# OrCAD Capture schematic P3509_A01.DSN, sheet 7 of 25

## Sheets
7 0018_CAMERA: size Custom
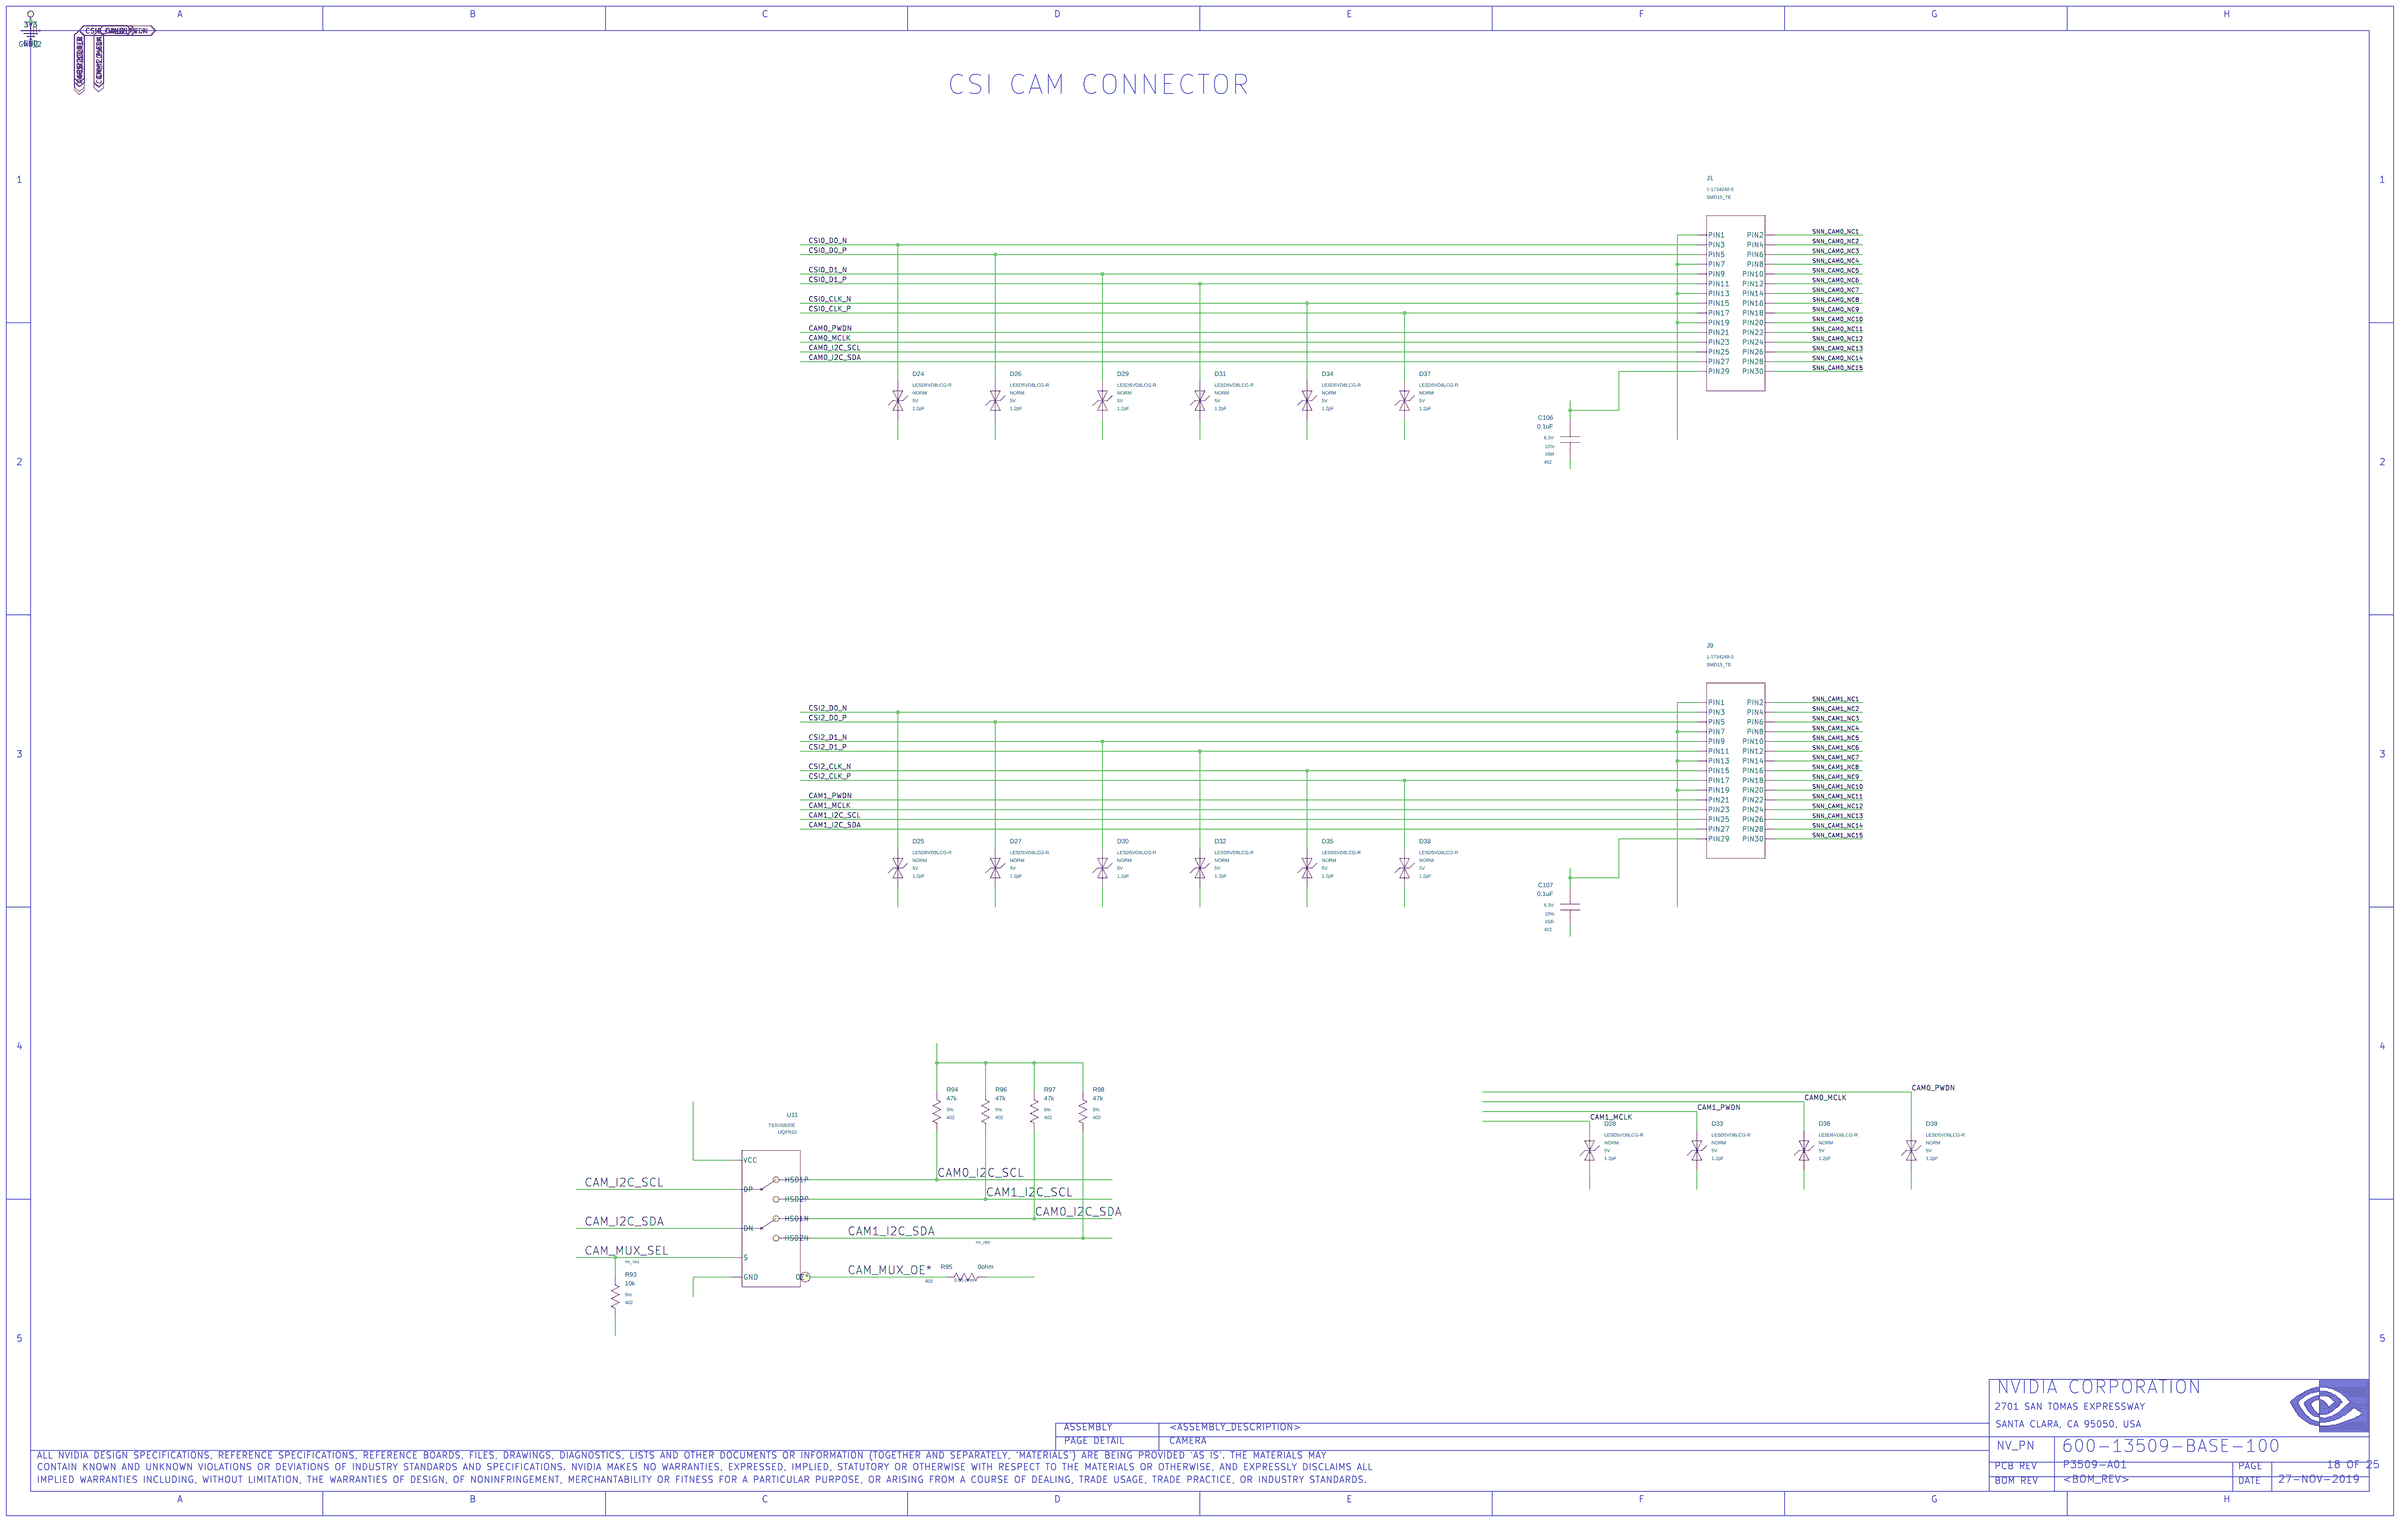
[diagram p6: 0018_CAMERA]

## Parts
C106  0.1uF  [402]
C107  0.1uF  [402]
D24  D_ESD  [DIODE_SMD_010X060]
D25  D_ESD  [DIODE_SMD_010X060]
D26  D_ESD  [DIODE_SMD_010X060]
D27  D_ESD  [DIODE_SMD_010X060]
D28  D_ESD  [DIODE_SMD_010X060]
D29  D_ESD  [DIODE_SMD_010X060]
D30  D_ESD  [DIODE_SMD_010X060]
D31  D_ESD  [DIODE_SMD_010X060]
D32  D_ESD  [DIODE_SMD_010X060]
D33  D_ESD  [DIODE_SMD_010X060]
D34  D_ESD  [DIODE_SMD_010X060]
D35  D_ESD  [DIODE_SMD_010X060]
D36  D_ESD  [DIODE_SMD_010X060]
D37  D_ESD  [DIODE_SMD_010X060]
D38  D_ESD  [DIODE_SMD_010X060]
D39  D_ESD  [DIODE_SMD_010X060]
J1  CON_FPC_15  [CON_FFC_030_SMD_ST_F_P010_ZIF]
J9  CON_FPC_15  [CON_FFC_030_SMD_ST_F_P010_ZIF]
R93  10k  [402]
R94  47k  [402]
R95  0ohm  [402]
R96  47k  [402]
R97  47k  [402]
R98  47k  [402]
U11  U_SW_ANA_USB  [QFN010R_P040_0018X0014]

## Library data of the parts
C106 = C#1_v2: ASSEMBLY: CAM; CDS_LIB: discrete; CDS_PART_NAME: C_0402-0.1UF,X5R,10%,6.3V,039-0007-000; CDS_PHYS_PART_NAME: C_0402-0.1UF,X5R,10%,6.3V,039-0007-000-0.1UF,039-0007-000; CDS_SEC: 1; CHIPS_PART_NAME: C; DEVICE_TYPENAME: C_0402-01UFX5R1063V039-0007-000-01UF039-0007-000; DRAWING: #NAME?; ESL: N/A; ESR: N/A; MAT: X5R; MAX_VOLTAGE: 6.3V; NV_PN: 039-0007-000; PATH: I89; PHYS_PAGE: 18; ROT: 2; SEC: 1; SIGNAL_MODEL: nv_cap; TOL: 10%; VER: 1; XY: (-4100,5400)
C107 = C#1_v2: ASSEMBLY: CAM; CDS_LIB: discrete; CDS_PART_NAME: C_0402-0.1UF,X5R,10%,6.3V,039-0007-000; CDS_PHYS_PART_NAME: C_0402-0.1UF,X5R,10%,6.3V,039-0007-000-0.1UF,039-0007-000; CDS_SEC: 1; CHIPS_PART_NAME: C; DEVICE_TYPENAME: C_0402-01UFX5R1063V039-0007-000-01UF039-0007-000; DRAWING: #NAME?; ESL: N/A; ESR: N/A; MAT: X5R; MAX_VOLTAGE: 6.3V; NV_PN: 039-0007-000; PATH: I94; PHYS_PAGE: 18; ROT: 2; SEC: 1; SIGNAL_MODEL: nv_cap; TOL: 10%; VER: 1; XY: (-4100,3000)
D24 = D_ESD: ASSEMBLY: CAM; BREAKDOWN_VOLTAGE_MIN_TYP: 5.5V; CAPACITANCE_MAX_TYP: 1.2pF; CDS_LIB: discrete; CDS_PART_NAME: D_ESD_NORM-LESD5VD8LCG-R,1 LINE,BI-DIRECTIONAL,5V,0.05UA,5.5V,10V@2A,1.2PF,090-0172-000; CDS_PHYS_PART_NAME: D_ESD_NORM-LESD5VD8LCG-R,1 LINE,BI-DIRECTIONAL,5V,0.05UA,5.5V,10V@2A,1.2PF,090-0172-000-090-0172-000; CDS_SEC: 1; CLAMPING_VOLTAGE: 10V@2A; CONFIGURATION: 1 Line; DEVICE_TYPENAME: D_ESD_NORM-LESD5VD8LCG-R1LINEBI-DIRECTIONAL5V005UA55V10V2A12PF090-0172-000-090-0172-000; DRAWING: #NAME?; MAX_REVERSE_LEAKAGE_CURRENT: 0.05uA; MAX_REVERSE_VOLTAGE: 5V; NV_NAME: LESD5VD8LCG-R; NV_PN: 090-0172-000; PACK_TYPE: NORM; PATH: I112; PHYS_PAGE: 18; POLARITY: Bi-Directional; ROT: 0; SEC: 1; VER: 2; XY: (-7550,5600)
D25 = D_ESD: ASSEMBLY: CAM; BREAKDOWN_VOLTAGE_MIN_TYP: 5.5V; CAPACITANCE_MAX_TYP: 1.2pF; CDS_LIB: discrete; CDS_PART_NAME: D_ESD_NORM-LESD5VD8LCG-R,1 LINE,BI-DIRECTIONAL,5V,0.05UA,5.5V,10V@2A,1.2PF,090-0172-000; CDS_PHYS_PART_NAME: D_ESD_NORM-LESD5VD8LCG-R,1 LINE,BI-DIRECTIONAL,5V,0.05UA,5.5V,10V@2A,1.2PF,090-0172-000-090-0172-000; CDS_SEC: 1; CLAMPING_VOLTAGE: 10V@2A; CONFIGURATION: 1 Line; DEVICE_TYPENAME: D_ESD_NORM-LESD5VD8LCG-R1LINEBI-DIRECTIONAL5V005UA55V10V2A12PF090-0172-000-090-0172-000; DRAWING: #NAME?; MAX_REVERSE_LEAKAGE_CURRENT: 0.05uA; MAX_REVERSE_VOLTAGE: 5V; NV_NAME: LESD5VD8LCG-R; NV_PN: 090-0172-000; PACK_TYPE: NORM; PATH: I146; PHYS_PAGE: 18; POLARITY: Bi-Directional; ROT: 0; SEC: 1; VER: 2; XY: (-7550,3200)
D26 = D_ESD: ASSEMBLY: CAM; BREAKDOWN_VOLTAGE_MIN_TYP: 5.5V; CAPACITANCE_MAX_TYP: 1.2pF; CDS_LIB: discrete; CDS_PART_NAME: D_ESD_NORM-LESD5VD8LCG-R,1 LINE,BI-DIRECTIONAL,5V,0.05UA,5.5V,10V@2A,1.2PF,090-0172-000; CDS_PHYS_PART_NAME: D_ESD_NORM-LESD5VD8LCG-R,1 LINE,BI-DIRECTIONAL,5V,0.05UA,5.5V,10V@2A,1.2PF,090-0172-000-090-0172-000; CDS_SEC: 1; CLAMPING_VOLTAGE: 10V@2A; CONFIGURATION: 1 Line; DEVICE_TYPENAME: D_ESD_NORM-LESD5VD8LCG-R1LINEBI-DIRECTIONAL5V005UA55V10V2A12PF090-0172-000-090-0172-000; DRAWING: #NAME?; MAX_REVERSE_LEAKAGE_CURRENT: 0.05uA; MAX_REVERSE_VOLTAGE: 5V; NV_NAME: LESD5VD8LCG-R; NV_PN: 090-0172-000; PACK_TYPE: NORM; PATH: I111; PHYS_PAGE: 18; POLARITY: Bi-Directional; ROT: 0; SEC: 1; VER: 2; XY: (-7050,5600)
D27 = D_ESD: ASSEMBLY: CAM; BREAKDOWN_VOLTAGE_MIN_TYP: 5.5V; CAPACITANCE_MAX_TYP: 1.2pF; CDS_LIB: discrete; CDS_PART_NAME: D_ESD_NORM-LESD5VD8LCG-R,1 LINE,BI-DIRECTIONAL,5V,0.05UA,5.5V,10V@2A,1.2PF,090-0172-000; CDS_PHYS_PART_NAME: D_ESD_NORM-LESD5VD8LCG-R,1 LINE,BI-DIRECTIONAL,5V,0.05UA,5.5V,10V@2A,1.2PF,090-0172-000-090-0172-000; CDS_SEC: 1; CLAMPING_VOLTAGE: 10V@2A; CONFIGURATION: 1 Line; DEVICE_TYPENAME: D_ESD_NORM-LESD5VD8LCG-R1LINEBI-DIRECTIONAL5V005UA55V10V2A12PF090-0172-000-090-0172-000; DRAWING: #NAME?; MAX_REVERSE_LEAKAGE_CURRENT: 0.05uA; MAX_REVERSE_VOLTAGE: 5V; NV_NAME: LESD5VD8LCG-R; NV_PN: 090-0172-000; PACK_TYPE: NORM; PATH: I144; PHYS_PAGE: 18; POLARITY: Bi-Directional; ROT: 0; SEC: 1; VER: 2; XY: (-7050,3200)
D28 = D_ESD: ASSEMBLY: CAM; BREAKDOWN_VOLTAGE_MIN_TYP: 5.5V; CAPACITANCE_MAX_TYP: 1.2pF; CDS_LIB: discrete; CDS_PART_NAME: D_ESD_NORM-LESD5VD8LCG-R,1 LINE,BI-DIRECTIONAL,5V,0.05UA,5.5V,10V@2A,1.2PF,090-0172-000; CDS_PHYS_PART_NAME: D_ESD_NORM-LESD5VD8LCG-R,1 LINE,BI-DIRECTIONAL,5V,0.05UA,5.5V,10V@2A,1.2PF,090-0172-000-090-0172-000; CDS_SEC: 1; CLAMPING_VOLTAGE: 10V@2A; CONFIGURATION: 1 Line; DEVICE_TYPENAME: D_ESD_NORM-LESD5VD8LCG-R1LINEBI-DIRECTIONAL5V005UA55V10V2A12PF090-0172-000-090-0172-000; DRAWING: #NAME?; MAX_REVERSE_LEAKAGE_CURRENT: 0.05uA; MAX_REVERSE_VOLTAGE: 5V; NV_NAME: LESD5VD8LCG-R; NV_PN: 090-0172-000; PACK_TYPE: NORM; PATH: I142; PHYS_PAGE: 18; POLARITY: Bi-Directional; ROT: 0; SEC: 1; VER: 2; XY: (-4000,1750)
D29 = D_ESD: ASSEMBLY: CAM; BREAKDOWN_VOLTAGE_MIN_TYP: 5.5V; CAPACITANCE_MAX_TYP: 1.2pF; CDS_LIB: discrete; CDS_PART_NAME: D_ESD_NORM-LESD5VD8LCG-R,1 LINE,BI-DIRECTIONAL,5V,0.05UA,5.5V,10V@2A,1.2PF,090-0172-000; CDS_PHYS_PART_NAME: D_ESD_NORM-LESD5VD8LCG-R,1 LINE,BI-DIRECTIONAL,5V,0.05UA,5.5V,10V@2A,1.2PF,090-0172-000-090-0172-000; CDS_SEC: 1; CLAMPING_VOLTAGE: 10V@2A; CONFIGURATION: 1 Line; DEVICE_TYPENAME: D_ESD_NORM-LESD5VD8LCG-R1LINEBI-DIRECTIONAL5V005UA55V10V2A12PF090-0172-000-090-0172-000; DRAWING: #NAME?; MAX_REVERSE_LEAKAGE_CURRENT: 0.05uA; MAX_REVERSE_VOLTAGE: 5V; NV_NAME: LESD5VD8LCG-R; NV_PN: 090-0172-000; PACK_TYPE: NORM; PATH: I108; PHYS_PAGE: 18; POLARITY: Bi-Directional; ROT: 0; SEC: 1; VER: 2; XY: (-6500,5600)
D30 = D_ESD: ASSEMBLY: CAM; BREAKDOWN_VOLTAGE_MIN_TYP: 5.5V; CAPACITANCE_MAX_TYP: 1.2pF; CDS_LIB: discrete; CDS_PART_NAME: D_ESD_NORM-LESD5VD8LCG-R,1 LINE,BI-DIRECTIONAL,5V,0.05UA,5.5V,10V@2A,1.2PF,090-0172-000; CDS_PHYS_PART_NAME: D_ESD_NORM-LESD5VD8LCG-R,1 LINE,BI-DIRECTIONAL,5V,0.05UA,5.5V,10V@2A,1.2PF,090-0172-000-090-0172-000; CDS_SEC: 1; CLAMPING_VOLTAGE: 10V@2A; CONFIGURATION: 1 Line; DEVICE_TYPENAME: D_ESD_NORM-LESD5VD8LCG-R1LINEBI-DIRECTIONAL5V005UA55V10V2A12PF090-0172-000-090-0172-000; DRAWING: #NAME?; MAX_REVERSE_LEAKAGE_CURRENT: 0.05uA; MAX_REVERSE_VOLTAGE: 5V; NV_NAME: LESD5VD8LCG-R; NV_PN: 090-0172-000; PACK_TYPE: NORM; PATH: I134; PHYS_PAGE: 18; POLARITY: Bi-Directional; ROT: 0; SEC: 1; VER: 2; XY: (-6500,3200)
D31 = D_ESD: ASSEMBLY: CAM; BREAKDOWN_VOLTAGE_MIN_TYP: 5.5V; CAPACITANCE_MAX_TYP: 1.2pF; CDS_LIB: discrete; CDS_PART_NAME: D_ESD_NORM-LESD5VD8LCG-R,1 LINE,BI-DIRECTIONAL,5V,0.05UA,5.5V,10V@2A,1.2PF,090-0172-000; CDS_PHYS_PART_NAME: D_ESD_NORM-LESD5VD8LCG-R,1 LINE,BI-DIRECTIONAL,5V,0.05UA,5.5V,10V@2A,1.2PF,090-0172-000-090-0172-000; CDS_SEC: 1; CLAMPING_VOLTAGE: 10V@2A; CONFIGURATION: 1 Line; DEVICE_TYPENAME: D_ESD_NORM-LESD5VD8LCG-R1LINEBI-DIRECTIONAL5V005UA55V10V2A12PF090-0172-000-090-0172-000; DRAWING: #NAME?; MAX_REVERSE_LEAKAGE_CURRENT: 0.05uA; MAX_REVERSE_VOLTAGE: 5V; NV_NAME: LESD5VD8LCG-R; NV_PN: 090-0172-000; PACK_TYPE: NORM; PATH: I107; PHYS_PAGE: 18; POLARITY: Bi-Directional; ROT: 0; SEC: 1; VER: 2; XY: (-6000,5600)
D32 = D_ESD: ASSEMBLY: CAM; BREAKDOWN_VOLTAGE_MIN_TYP: 5.5V; CAPACITANCE_MAX_TYP: 1.2pF; CDS_LIB: discrete; CDS_PART_NAME: D_ESD_NORM-LESD5VD8LCG-R,1 LINE,BI-DIRECTIONAL,5V,0.05UA,5.5V,10V@2A,1.2PF,090-0172-000; CDS_PHYS_PART_NAME: D_ESD_NORM-LESD5VD8LCG-R,1 LINE,BI-DIRECTIONAL,5V,0.05UA,5.5V,10V@2A,1.2PF,090-0172-000-090-0172-000; CDS_SEC: 1; CLAMPING_VOLTAGE: 10V@2A; CONFIGURATION: 1 Line; DEVICE_TYPENAME: D_ESD_NORM-LESD5VD8LCG-R1LINEBI-DIRECTIONAL5V005UA55V10V2A12PF090-0172-000-090-0172-000; DRAWING: #NAME?; MAX_REVERSE_LEAKAGE_CURRENT: 0.05uA; MAX_REVERSE_VOLTAGE: 5V; NV_NAME: LESD5VD8LCG-R; NV_PN: 090-0172-000; PACK_TYPE: NORM; PATH: I132; PHYS_PAGE: 18; POLARITY: Bi-Directional; ROT: 0; SEC: 1; VER: 2; XY: (-6000,3200)
D33 = D_ESD: ASSEMBLY: CAM; BREAKDOWN_VOLTAGE_MIN_TYP: 5.5V; CAPACITANCE_MAX_TYP: 1.2pF; CDS_LIB: discrete; CDS_PART_NAME: D_ESD_NORM-LESD5VD8LCG-R,1 LINE,BI-DIRECTIONAL,5V,0.05UA,5.5V,10V@2A,1.2PF,090-0172-000; CDS_PHYS_PART_NAME: D_ESD_NORM-LESD5VD8LCG-R,1 LINE,BI-DIRECTIONAL,5V,0.05UA,5.5V,10V@2A,1.2PF,090-0172-000-090-0172-000; CDS_SEC: 1; CLAMPING_VOLTAGE: 10V@2A; CONFIGURATION: 1 Line; DEVICE_TYPENAME: D_ESD_NORM-LESD5VD8LCG-R1LINEBI-DIRECTIONAL5V005UA55V10V2A12PF090-0172-000-090-0172-000; DRAWING: #NAME?; MAX_REVERSE_LEAKAGE_CURRENT: 0.05uA; MAX_REVERSE_VOLTAGE: 5V; NV_NAME: LESD5VD8LCG-R; NV_PN: 090-0172-000; PACK_TYPE: NORM; PATH: I140; PHYS_PAGE: 18; POLARITY: Bi-Directional; ROT: 0; SEC: 1; VER: 2; XY: (-3450,1750)
D34 = D_ESD: ASSEMBLY: CAM; BREAKDOWN_VOLTAGE_MIN_TYP: 5.5V; CAPACITANCE_MAX_TYP: 1.2pF; CDS_LIB: discrete; CDS_PART_NAME: D_ESD_NORM-LESD5VD8LCG-R,1 LINE,BI-DIRECTIONAL,5V,0.05UA,5.5V,10V@2A,1.2PF,090-0172-000; CDS_PHYS_PART_NAME: D_ESD_NORM-LESD5VD8LCG-R,1 LINE,BI-DIRECTIONAL,5V,0.05UA,5.5V,10V@2A,1.2PF,090-0172-000-090-0172-000; CDS_SEC: 1; CLAMPING_VOLTAGE: 10V@2A; CONFIGURATION: 1 Line; DEVICE_TYPENAME: D_ESD_NORM-LESD5VD8LCG-R1LINEBI-DIRECTIONAL5V005UA55V10V2A12PF090-0172-000-090-0172-000; DRAWING: #NAME?; MAX_REVERSE_LEAKAGE_CURRENT: 0.05uA; MAX_REVERSE_VOLTAGE: 5V; NV_NAME: LESD5VD8LCG-R; NV_PN: 090-0172-000; PACK_TYPE: NORM; PATH: I103; PHYS_PAGE: 18; POLARITY: Bi-Directional; ROT: 0; SEC: 1; VER: 2; XY: (-5450,5600)
D35 = D_ESD: ASSEMBLY: CAM; BREAKDOWN_VOLTAGE_MIN_TYP: 5.5V; CAPACITANCE_MAX_TYP: 1.2pF; CDS_LIB: discrete; CDS_PART_NAME: D_ESD_NORM-LESD5VD8LCG-R,1 LINE,BI-DIRECTIONAL,5V,0.05UA,5.5V,10V@2A,1.2PF,090-0172-000; CDS_PHYS_PART_NAME: D_ESD_NORM-LESD5VD8LCG-R,1 LINE,BI-DIRECTIONAL,5V,0.05UA,5.5V,10V@2A,1.2PF,090-0172-000-090-0172-000; CDS_SEC: 1; CLAMPING_VOLTAGE: 10V@2A; CONFIGURATION: 1 Line; DEVICE_TYPENAME: D_ESD_NORM-LESD5VD8LCG-R1LINEBI-DIRECTIONAL5V005UA55V10V2A12PF090-0172-000-090-0172-000; DRAWING: #NAME?; MAX_REVERSE_LEAKAGE_CURRENT: 0.05uA; MAX_REVERSE_VOLTAGE: 5V; NV_NAME: LESD5VD8LCG-R; NV_PN: 090-0172-000; PACK_TYPE: NORM; PATH: I131; PHYS_PAGE: 18; POLARITY: Bi-Directional; ROT: 0; SEC: 1; VER: 2; XY: (-5450,3200)
D36 = D_ESD: ASSEMBLY: CAM; BREAKDOWN_VOLTAGE_MIN_TYP: 5.5V; CAPACITANCE_MAX_TYP: 1.2pF; CDS_LIB: discrete; CDS_PART_NAME: D_ESD_NORM-LESD5VD8LCG-R,1 LINE,BI-DIRECTIONAL,5V,0.05UA,5.5V,10V@2A,1.2PF,090-0172-000; CDS_PHYS_PART_NAME: D_ESD_NORM-LESD5VD8LCG-R,1 LINE,BI-DIRECTIONAL,5V,0.05UA,5.5V,10V@2A,1.2PF,090-0172-000-090-0172-000; CDS_SEC: 1; CLAMPING_VOLTAGE: 10V@2A; CONFIGURATION: 1 Line; DEVICE_TYPENAME: D_ESD_NORM-LESD5VD8LCG-R1LINEBI-DIRECTIONAL5V005UA55V10V2A12PF090-0172-000-090-0172-000; DRAWING: #NAME?; MAX_REVERSE_LEAKAGE_CURRENT: 0.05uA; MAX_REVERSE_VOLTAGE: 5V; NV_NAME: LESD5VD8LCG-R; NV_PN: 090-0172-000; PACK_TYPE: NORM; PATH: I138; PHYS_PAGE: 18; POLARITY: Bi-Directional; ROT: 0; SEC: 1; VER: 2; XY: (-2900,1750)
D37 = D_ESD: ASSEMBLY: CAM; BREAKDOWN_VOLTAGE_MIN_TYP: 5.5V; CAPACITANCE_MAX_TYP: 1.2pF; CDS_LIB: discrete; CDS_PART_NAME: D_ESD_NORM-LESD5VD8LCG-R,1 LINE,BI-DIRECTIONAL,5V,0.05UA,5.5V,10V@2A,1.2PF,090-0172-000; CDS_PHYS_PART_NAME: D_ESD_NORM-LESD5VD8LCG-R,1 LINE,BI-DIRECTIONAL,5V,0.05UA,5.5V,10V@2A,1.2PF,090-0172-000-090-0172-000; CDS_SEC: 1; CLAMPING_VOLTAGE: 10V@2A; CONFIGURATION: 1 Line; DEVICE_TYPENAME: D_ESD_NORM-LESD5VD8LCG-R1LINEBI-DIRECTIONAL5V005UA55V10V2A12PF090-0172-000-090-0172-000; DRAWING: #NAME?; MAX_REVERSE_LEAKAGE_CURRENT: 0.05uA; MAX_REVERSE_VOLTAGE: 5V; NV_NAME: LESD5VD8LCG-R; NV_PN: 090-0172-000; PACK_TYPE: NORM; PATH: I102; PHYS_PAGE: 18; POLARITY: Bi-Directional; ROT: 0; SEC: 1; VER: 2; XY: (-4950,5600)
D38 = D_ESD: ASSEMBLY: CAM; BREAKDOWN_VOLTAGE_MIN_TYP: 5.5V; CAPACITANCE_MAX_TYP: 1.2pF; CDS_LIB: discrete; CDS_PART_NAME: D_ESD_NORM-LESD5VD8LCG-R,1 LINE,BI-DIRECTIONAL,5V,0.05UA,5.5V,10V@2A,1.2PF,090-0172-000; CDS_PHYS_PART_NAME: D_ESD_NORM-LESD5VD8LCG-R,1 LINE,BI-DIRECTIONAL,5V,0.05UA,5.5V,10V@2A,1.2PF,090-0172-000-090-0172-000; CDS_SEC: 1; CLAMPING_VOLTAGE: 10V@2A; CONFIGURATION: 1 Line; DEVICE_TYPENAME: D_ESD_NORM-LESD5VD8LCG-R1LINEBI-DIRECTIONAL5V005UA55V10V2A12PF090-0172-000-090-0172-000; DRAWING: #NAME?; MAX_REVERSE_LEAKAGE_CURRENT: 0.05uA; MAX_REVERSE_VOLTAGE: 5V; NV_NAME: LESD5VD8LCG-R; NV_PN: 090-0172-000; PACK_TYPE: NORM; PATH: I129; PHYS_PAGE: 18; POLARITY: Bi-Directional; ROT: 0; SEC: 1; VER: 2; XY: (-4950,3200)
D39 = D_ESD: ASSEMBLY: CAM; BREAKDOWN_VOLTAGE_MIN_TYP: 5.5V; CAPACITANCE_MAX_TYP: 1.2pF; CDS_LIB: discrete; CDS_PART_NAME: D_ESD_NORM-LESD5VD8LCG-R,1 LINE,BI-DIRECTIONAL,5V,0.05UA,5.5V,10V@2A,1.2PF,090-0172-000; CDS_PHYS_PART_NAME: D_ESD_NORM-LESD5VD8LCG-R,1 LINE,BI-DIRECTIONAL,5V,0.05UA,5.5V,10V@2A,1.2PF,090-0172-000-090-0172-000; CDS_SEC: 1; CLAMPING_VOLTAGE: 10V@2A; CONFIGURATION: 1 Line; DEVICE_TYPENAME: D_ESD_NORM-LESD5VD8LCG-R1LINEBI-DIRECTIONAL5V005UA55V10V2A12PF090-0172-000-090-0172-000; DRAWING: #NAME?; MAX_REVERSE_LEAKAGE_CURRENT: 0.05uA; MAX_REVERSE_VOLTAGE: 5V; NV_NAME: LESD5VD8LCG-R; NV_PN: 090-0172-000; PACK_TYPE: NORM; PATH: I136; PHYS_PAGE: 18; POLARITY: Bi-Directional; ROT: 0; SEC: 1; VER: 2; XY: (-2350,1750)
J1 = CON_FPC_15: ANGLE: 0; ASSEMBLY: CAM; CDS_LIB: electro_mechanic; CDS_PART_NAME: CON_FPC_15_SMD15_TE-1-1734248-5,FEMALE,1MM,0,YES,YES,[ ],NO,NO,N/A,N/A,080-1669-000; CDS_PHYS_PART_NAME: CON_FPC_15_SMD15_TE-1-1734248-5,FEMALE,1MM,0,YES,YES,[ ],NO,NO,N/A,N/A,080-1669-000-080-1669-000; CDS_SEC: 1; DEVICE_TYPENAME: CON_FPC_15_SMD15_TE-1-1734248-5FEMALE1MM0YESYESNONONANA080-1669-000-080-1669-000; DRAWING: #NAME?; EMI_GROUND_TAB: No; GENDER: Female; LATCHING: [ ]; MAX_CURRENT: N/A; MAX_VOLTAGE: N/A; NV_NAME: 1-1734248-5; NV_PN: 080-1669-000; PACK_TYPE: SMD15_TE; PATH: I86; PHYS_PAGE: 18; PITCH: 1mm; REFLOW: Yes; ROT: 0; SEC: 1; SEC_TYPE: SMD15_TE; SHIELDED: No; SHROUDED: YES; VER: 3; XY: (-3250,6100)
J9 = CON_FPC_15: ANGLE: 0; ASSEMBLY: CAM; CDS_LIB: electro_mechanic; CDS_PART_NAME: CON_FPC_15_SMD15_TE-1-1734248-5,FEMALE,1MM,0,YES,YES,[ ],NO,NO,N/A,N/A,080-1669-000; CDS_PHYS_PART_NAME: CON_FPC_15_SMD15_TE-1-1734248-5,FEMALE,1MM,0,YES,YES,[ ],NO,NO,N/A,N/A,080-1669-000-080-1669-000; CDS_SEC: 1; DEVICE_TYPENAME: CON_FPC_15_SMD15_TE-1-1734248-5FEMALE1MM0YESYESNONONANA080-1669-000-080-1669-000; DRAWING: #NAME?; EMI_GROUND_TAB: No; GENDER: Female; LATCHING: [ ]; MAX_CURRENT: N/A; MAX_VOLTAGE: N/A; NV_NAME: 1-1734248-5; NV_PN: 080-1669-000; PACK_TYPE: SMD15_TE; PATH: I91; PHYS_PAGE: 18; PITCH: 1mm; REFLOW: Yes; ROT: 0; SEC: 1; SHIELDED: No; SHROUDED: YES; VER: 3; XY: (-3250,3700)
R93 = R: ASSEMBLY: CAM; CDS_LIB: discrete; CDS_PART_NAME: R_0402-10K,5 %,62.5MW,195-0486-000; CDS_PHYS_PART_NAME: R_0402-10K,5 %,62.5MW,195-0486-000-10K,195-0486-000; CDS_SEC: 1; DEVICE_TYPENAME: R_0402-10K5625MW195-0486-000-10K195-0486-000; DRAWING: #NAME?; MAX_WATTAGE: 62.5mW; NV_PN: 195-0486-000; PATH: I82; PHYS_PAGE: 18; ROT: 0; SEC: 1; SIGNAL_MODEL: nv_res; TOL: 5%; VER: 2; XY: (-9000,1000)
R94 = R: ASSEMBLY: CAM; CDS_LIB: discrete; CDS_PART_NAME: R_0402-47K,5 %,62.5MW,195-0599-000; CDS_PHYS_PART_NAME: R_0402-47K,5 %,62.5MW,195-0599-000-195-0599-000,47K; CDS_SEC: 1; DEVICE_TYPENAME: R_0402-47K5625MW195-0599-000-195-0599-00047K; DRAWING: #NAME?; MAX_WATTAGE: 62.5mW; NV_PN: 195-0599-000; PATH: I75; PHYS_PAGE: 18; ROT: 0; SEC: 1; SIGNAL_MODEL: nv_res; TOL: 5%; VER: 2; XY: (-7350,1950)
R95 = R#1: ASSEMBLY: CAM; CDS_LIB: discrete; CDS_PART_NAME: R_0402-0OHM,0.05 OHM,62.5MW,195-2655-000; CDS_PHYS_PART_NAME: R_0402-0OHM,0.05 OHM,62.5MW,195-2655-000-0OHM,195-2655-000; CDS_SEC: 1; CHIPS_PART_NAME: R; DEVICE_TYPENAME: R_0402-0OHM005OHM625MW195-2655-000-0OHM195-2655-000; DRAWING: #NAME?; MAX_WATTAGE: 62.5mW; NV_PN: 195-2655-000; PATH: I77; PHYS_PAGE: 18; ROT: 0; SEC: 1; SIGNAL_MODEL: nv_res; TOL: 0.05 ohm; VER: 1; XY: (-7200,1100)
R96 = R: ASSEMBLY: CAM; CDS_LIB: discrete; CDS_PART_NAME: R_0402-47K,5 %,62.5MW,195-0599-000; CDS_PHYS_PART_NAME: R_0402-47K,5 %,62.5MW,195-0599-000-195-0599-000,47K; CDS_SEC: 1; DEVICE_TYPENAME: R_0402-47K5625MW195-0599-000-195-0599-00047K; DRAWING: #NAME?; MAX_WATTAGE: 62.5mW; NV_PN: 195-0599-000; PATH: I74; PHYS_PAGE: 18; ROT: 0; SEC: 1; SIGNAL_MODEL: nv_res; TOL: 5%; VER: 2; XY: (-7100,1950)
R97 = R: ASSEMBLY: CAM; CDS_LIB: discrete; CDS_PART_NAME: R_0402-47K,5 %,62.5MW,195-0599-000; CDS_PHYS_PART_NAME: R_0402-47K,5 %,62.5MW,195-0599-000-195-0599-000,47K; CDS_SEC: 1; DEVICE_TYPENAME: R_0402-47K5625MW195-0599-000-195-0599-00047K; DRAWING: #NAME?; MAX_WATTAGE: 62.5mW; NV_PN: 195-0599-000; PATH: I72; PHYS_PAGE: 18; ROT: 0; SEC: 1; SIGNAL_MODEL: nv_res; TOL: 5%; VER: 2; XY: (-6850,1950)
R98 = R: ASSEMBLY: CAM; CDS_LIB: discrete; CDS_PART_NAME: R_0402-47K,5 %,62.5MW,195-0599-000; CDS_PHYS_PART_NAME: R_0402-47K,5 %,62.5MW,195-0599-000-195-0599-000,47K; CDS_SEC: 1; DEVICE_TYPENAME: R_0402-47K5625MW195-0599-000-195-0599-00047K; DRAWING: #NAME?; MAX_WATTAGE: 62.5mW; NV_PN: 195-0599-000; PATH: I71; PHYS_PAGE: 18; ROT: 0; SEC: 1; SIGNAL_MODEL: nv_res; TOL: 5%; VER: 2; XY: (-6600,1950)
U11 = U_SW_ANA_USB: ASSEMBLY: CAM; CDS_LIB: analog; CDS_PART_NAME: U_SW_ANA_USB_UQFN10-TS3USB30E,SWITCH - ANALOG,115-0655-000; CDS_PHYS_PART_NAME: U_SW_ANA_USB_UQFN10-TS3USB30E,SWITCH - ANALOG,115-0655-000-115-0655-000; CDS_SEC: 1; DEVICE_TYPENAME: U_SW_ANA_USB_UQFN10-TS3USB30ESWITCH-ANALOG115-0655-000-115-0655-000; DRAWING: #NAME?; FUNCTION: Switch - Analog; NV_NAME: TS3USB30E; NV_PN: 115-0655-000; PACK_TYPE: UQFN10; PATH: I79; PHYS_PAGE: 18; ROT: 2; SEC: 1; VER: 3; XY: (-8200,1400)

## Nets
GND: C106.2 C107.2 D24.2 D25.2 D26.2 D27.2 D28.2 D29.2 D30.2 D31.2 D32.2 D33.2 D34.2 D35.2 D36.2 D37.2 D38.2 D39.2 J1.1(PIN1) J1.7(PIN7) J1.13(PIN13) J1.19(PIN19) J9.1(PIN1) J9.7(PIN7) J9.13(PIN13) J9.19(PIN19) R93.2 R95.2 U11.4(GND) ; also on sheet 1 2 3 4 5 6 8 9 10 11 12 13 14 15 16 17 18 19 21
VDD_3V3_SYS: C106.1 C107.1 J1.29(PIN29) J9.29(PIN29) R94.1 R96.1 R97.1 R98.1 U11.9(VCC) ; also on sheet 2 3 4 5 6 8 9 12 15 16 19 20 21
CAM0_I2C_SCL: J1.25(PIN25) R94.2 U11.1(HSD1P)
CAM0_I2C_SDA: J1.27(PIN27) R97.2 U11.7(HSD1N)
CAM0_MCLK: D36.1 J1.23(PIN23) ; also on sheet 20
CAM0_PWDN: D39.1 J1.21(PIN21) ; also on sheet 20
CAM1_I2C_SCL: J9.25(PIN25) R96.2 U11.2(HSD2P)
CAM1_I2C_SDA: J9.27(PIN27) R98.2 U11.6(HSD2N)
CAM1_MCLK: D28.1 J9.23(PIN23) ; also on sheet 20
CAM1_PWDN: D33.1 J9.21(PIN21) ; also on sheet 20
CAM_I2C_SCL: U11.3(DP) ; also on sheet 12 20
CAM_I2C_SDA: U11.5(DN) ; also on sheet 12 20
CAM_MUX_OE*: R95.1 U11.8(OE*)
CAM_MUX_SEL: R93.1 U11.10(S) ; also on sheet 20
CSI0_CLK_N: D34.1 J1.15(PIN15) ; also on sheet 20
CSI0_CLK_P: D37.1 J1.17(PIN17) ; also on sheet 20
CSI0_D0_N: D24.1 J1.3(PIN3) ; also on sheet 20
CSI0_D0_P: D26.1 J1.5(PIN5) ; also on sheet 20
CSI0_D1_N: D29.1 J1.9(PIN9) ; also on sheet 20
CSI0_D1_P: D31.1 J1.11(PIN11) ; also on sheet 20
CSI2_CLK_N: D35.1 J9.15(PIN15) ; also on sheet 20
CSI2_CLK_P: D38.1 J9.17(PIN17) ; also on sheet 20
CSI2_D0_N: D25.1 J9.3(PIN3) ; also on sheet 20
CSI2_D0_P: D27.1 J9.5(PIN5) ; also on sheet 20
CSI2_D1_N: D30.1 J9.9(PIN9) ; also on sheet 20
CSI2_D1_P: D32.1 J9.11(PIN11) ; also on sheet 20
SNN_CAM0_NC1: J1.2(PIN2)
SNN_CAM0_NC2: J1.4(PIN4)
SNN_CAM0_NC3: J1.6(PIN6)
SNN_CAM0_NC4: J1.8(PIN8)
SNN_CAM0_NC5: J1.10(PIN10)
SNN_CAM0_NC6: J1.12(PIN12)
SNN_CAM0_NC7: J1.14(PIN14)
SNN_CAM0_NC8: J1.16(PIN16)
SNN_CAM0_NC9: J1.18(PIN18)
SNN_CAM0_NC10: J1.20(PIN20)
SNN_CAM0_NC11: J1.22(PIN22)
SNN_CAM0_NC12: J1.24(PIN24)
SNN_CAM0_NC13: J1.26(PIN26)
SNN_CAM0_NC14: J1.28(PIN28)
SNN_CAM0_NC15: J1.30(PIN30)
SNN_CAM1_NC1: J9.2(PIN2)
SNN_CAM1_NC2: J9.4(PIN4)
SNN_CAM1_NC3: J9.6(PIN6)
SNN_CAM1_NC4: J9.8(PIN8)
SNN_CAM1_NC5: J9.10(PIN10)
SNN_CAM1_NC6: J9.12(PIN12)
SNN_CAM1_NC7: J9.14(PIN14)
SNN_CAM1_NC8: J9.16(PIN16)
SNN_CAM1_NC9: J9.18(PIN18)
SNN_CAM1_NC10: J9.20(PIN20)
SNN_CAM1_NC11: J9.22(PIN22)
SNN_CAM1_NC12: J9.24(PIN24)
SNN_CAM1_NC13: J9.26(PIN26)
SNN_CAM1_NC14: J9.28(PIN28)
SNN_CAM1_NC15: J9.30(PIN30)

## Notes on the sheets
sheet 7
- A
- B
- C
- D
- E
- F
- G
- H
- CSI CAM CONNECTOR
- 1
- 1
- 2
- 2
- 3
- 3
- 4
- 4
- 5
- 5
- NVIDIA CORPORATION
- 2701 SAN TOMAS EXPRESSWAY
- ASSEMBLY
- <ASSEMBLY_DESCRIPTION>
- SANTA CLARA, CA 95050, USA
- PAGE DETAIL
- CAMERA
- NV_PN
- 600-13509-BASE-100
- ALL NVIDIA DESIGN SPECIFICATIONS, REFERENCE SPECIFICATIONS, REFERENCE BOARDS, FILES, DRAWINGS, DIAGNOSTICS, LISTS AND OTHER DOCUMENTS OR INFORMATION (TOGETHER AND SEPARATELY, 'MATERIALS') ARE BEING PROVIDED 'AS IS'. THE MATERIALS MAY
- CONTAIN KNOWN AND UNKNOWN VIOLATIONS OR DEVIATIONS OF INDUSTRY STANDARDS AND SPECIFICATIONS. NVIDIA MAKES NO WARRANTIES, EXPRESSED, IMPLIED, STATUTORY OR OTHERWISE WITH RESPECT TO THE MATERIALS OR OTHERWISE, AND EXPRESSLY DISCLAIMS ALL
- PCB REV
- P3509-A01
- PAGE
- 18 OF 25
- IMPLIED WARRANTIES INCLUDING, WITHOUT LIMITATION, THE WARRANTIES OF DESIGN, OF NONINFRINGEMENT, MERCHANTABILITY OR FITNESS FOR A PARTICULAR PURPOSE, OR ARISING FROM A COURSE OF DEALING, TRADE USAGE, TRADE PRACTICE, OR INDUSTRY STANDARDS.
- BOM REV
- <BOM_REV>
- DATE
- 27-NOV-2019
- A
- B
- C
- D
- E
- F
- G
- H
